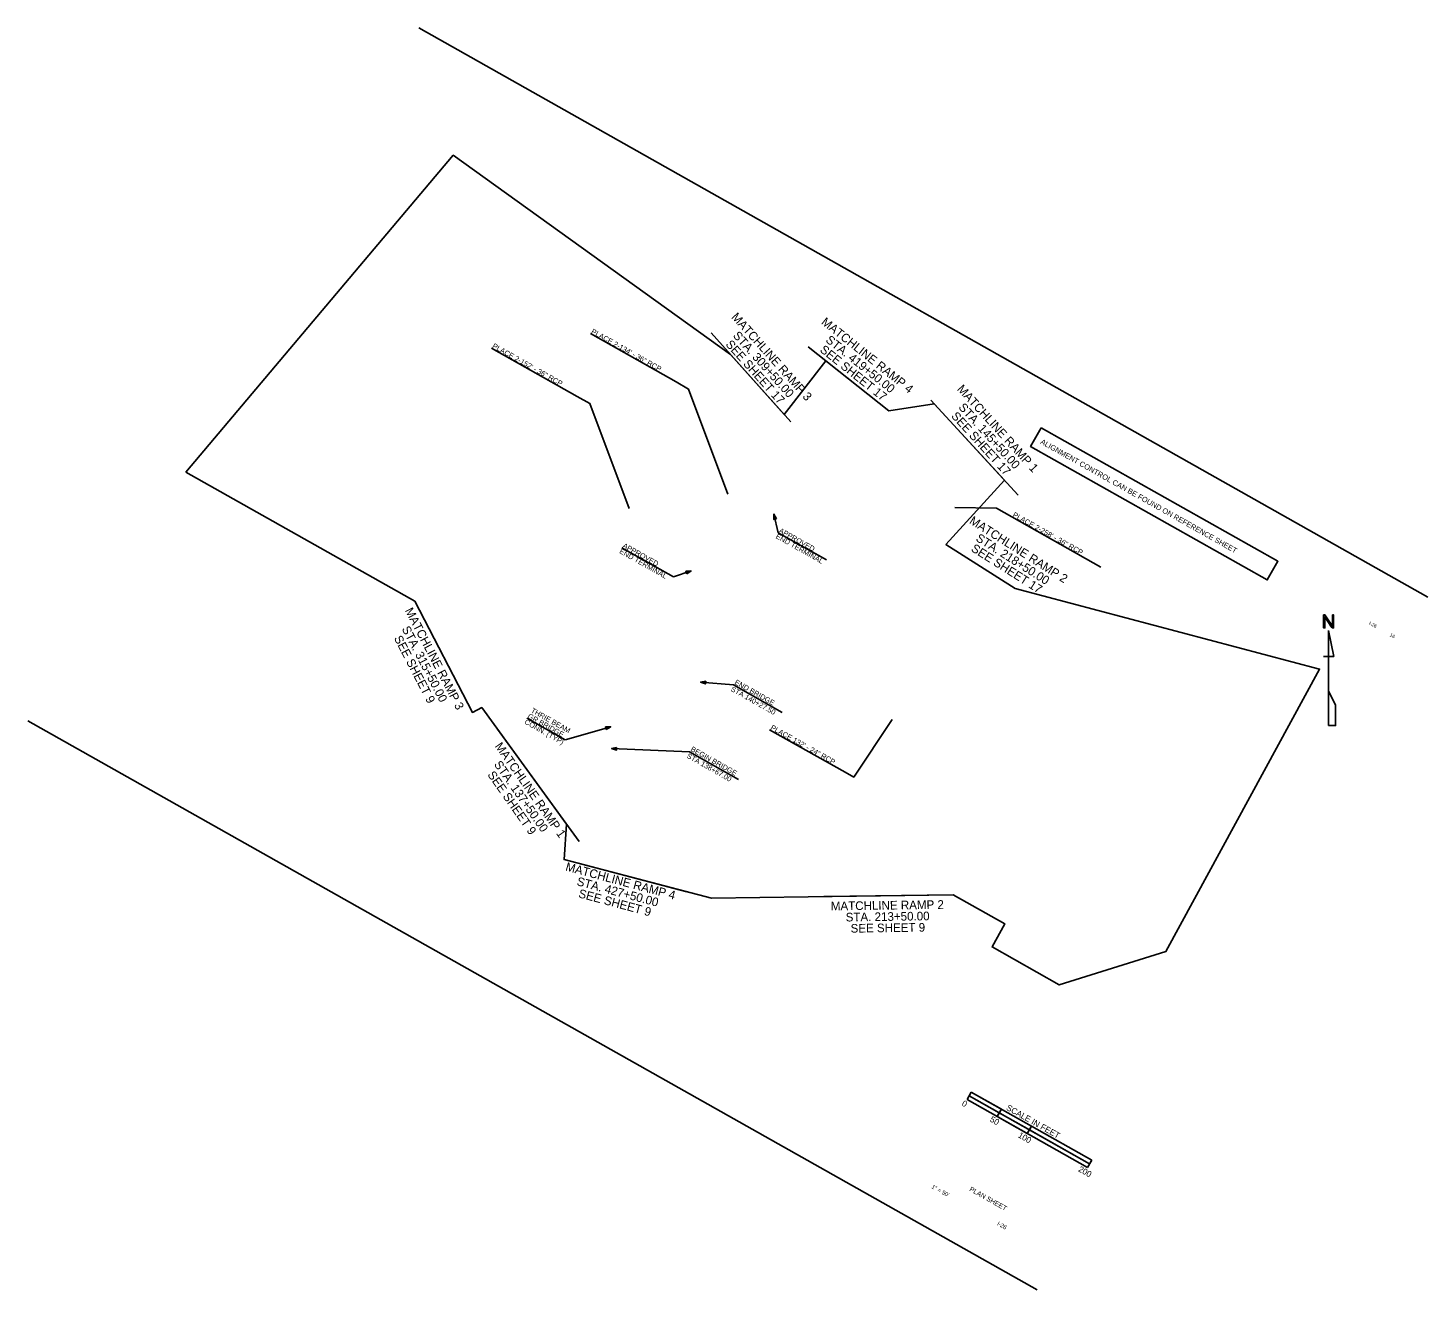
# Model space of a CAD drawing. Extents: x 2220815 to 2222839, y 468833 to 470658.
import ezdxf

# ---------------------------------------------------------------- set-up
doc = ezdxf.new("R2010")
doc.units = 0
for name, color, linetype in [('North Arrow', 7, 'Continuous'), ('RD_HY_Misc', 7, 'Continuous'), ('RD_PD_Final_TX', 7, 'Continuous'), ('RD_SHT_MatchLine', 7, 'Continuous'), ('RD_SHT_ShtClip', 7, 'Continuous'), ('RD_SHT_TX', 7, 'Continuous')]:
    doc.layers.add(name, color=color, linetype=linetype)

msp = doc.modelspace()

# ---------------------------------------------------------------- linework, layer by layer
at = {"layer": 'North Arrow'}
for p, q in [((2222695.4, 469786.6), (2222695.4, 469749.1)), ((2222702.9, 469749.1), (2222695.4, 469786.6)), ((2222695.4, 469749.1), (2222687.9, 469749.1)), ((2222695.4, 469749.1), (2222695.4, 469699.1)), ((2222695.4, 469749.1), (2222702.9, 469749.1)), ((2222695.4, 469699.1), (2222695.4, 469649.1))]:
    msp.add_line(p, q, dxfattribs=at)
for points in [[(2222688.2, 469793), (2222688.2, 469790.3), (2222689.9, 469790.3), (2222689.9, 469793), (2222689.9, 469806.5), (2222691.9, 469806.5), (2222690.1, 469809.1), (2222688.2, 469809.1), (2222688.2, 469806.5)], [(2222698.8, 469793), (2222700.6, 469790.3), (2222702.5, 469790.3), (2222702.5, 469793), (2222700.8, 469793), (2222691.9, 469806.5), (2222689.9, 469806.5)], [(2222700.8, 469809.1), (2222700.8, 469793), (2222702.5, 469793), (2222702.5, 469809.1)]]:
    msp.add_lwpolyline(points, close=True, dxfattribs=at)
msp.add_lwpolyline([(2222695.4, 469649.1), (2222705.4, 469649.1), (2222705.4, 469679.1), (2222695.4, 469699.1)], dxfattribs=at)
at = {"layer": 'RD_HY_Misc'}
for p, q in [((2221752.1, 470145.9), (2221628.1, 470215.9)), ((2221609.1, 470125), (2221485.1, 470194.9)), ((2222365.9, 469878.3), (2222237.3, 469950.9)), ((2221996.6, 469581.6), (2221887.3, 469643.2))]:
    msp.add_line(p, q, dxfattribs=at)
for points in [[(2221752.1, 470145.9), (2221770.2, 470135.7), (2221826.9, 469983.9)], [(2221609.1, 470125), (2221627.2, 470114.8), (2221684, 469962.9)], [(2222237.3, 469950.9), (2222215, 469963.5), (2222155.1, 469964.4)], [(2221996.6, 469581.6), (2222008.8, 469574.7), (2222064.6, 469657.9)]]:
    msp.add_lwpolyline(points, dxfattribs=at)
at = {"layer": 'RD_PD_Final_TX'}
for p, q in [((2221969.3, 469888.6), (2221899.5, 469928)), ((2221748.1, 469864.3), (2221673.5, 469906.3)), ((2221905.5, 469668), (2221834.9, 469707.9)), ((2221591.6, 469628.5), (2221536.2, 469659.7)), ((2221842.3, 469571.2), (2221771.3, 469611.3))]:
    msp.add_line(p, q, dxfattribs=at)
for points in [[(2221897, 469948.1), (2221893.5, 469954.8), (2221893.2, 469947.3)], [(2221767.4, 469868.6), (2221773.7, 469872.7), (2221766.2, 469872.3)], [(2221794.8, 469713.2), (2221787.4, 469711.9), (2221794.4, 469709.3)], [(2221651.1, 469643.5), (2221657.5, 469647.4), (2221650, 469647.3)], [(2221666.1, 469617.5), (2221658.7, 469615.9), (2221665.9, 469613.7)]]:
    msp.add_lwpolyline(points, close=True, dxfattribs=at)
for points in [[(2221899.5, 469928), (2221893.5, 469954.8)], [(2221748.1, 469864.3), (2221773.7, 469872.7)], [(2221834.9, 469707.9), (2221787.4, 469711.9)], [(2221591.6, 469628.5), (2221657.5, 469647.4)], [(2221771.3, 469611.3), (2221658.7, 469615.9)]]:
    msp.add_lwpolyline(points, dxfattribs=at)
at = {"layer": 'RD_SHT_MatchLine'}
for p, q in [((2221802.7, 470216.9), (2221917.8, 470088.2)), ((2221942.9, 470196.7), (2222059.8, 470104.2)), ((2222246.8, 469982.2), (2222120.3, 470119.7)), ((2222242.2, 469847.5), (2222142.2, 469911)), ((2221374.2, 469828.9), (2221457.6, 469668.2)), ((2221611.8, 469481.5), (2221493.8, 469643.8)), ((2221767.5, 469408.8), (2221590, 469455.3)), ((2222152.8, 469404.5), (2221965.7, 469401.8))]:
    msp.add_line(p, q, dxfattribs=at)
at = {"layer": 'RD_SHT_ShtClip'}
msp.add_lwpolyline([(2221043.3, 470015.5), (2221374.2, 469828.9), (2221457.6, 469668.2), (2221471, 469675.1), (2221593.4, 469506.8), (2221590, 469455.3), (2221803.1, 469399.5), (2222152.8, 469404.5), (2222227.5, 469362.4), (2222208.8, 469329.2), (2222306, 469274.3), (2222460.1, 469322.7), (2222682.3, 469730.7), (2222242.2, 469847.5), (2222142.2, 469911), (2222226.7, 470004.1), (2222125.2, 470114.4), (2222059.8, 470104.2), (2221968.4, 470176.5), (2221908.2, 470098.9), (2221830.9, 470185.4), (2221430, 470473.8)], close=True, dxfattribs=at)
at = {"layer": 'RD_SHT_TX'}
for p, q in [((2222839, 469834.7), (2221380.2, 470657.7)), ((2220815.1, 469656.1), (2222274, 468833.1)), ((2222178.8, 469119.3), (2222172.6, 469108.4)), ((2222172.6, 469108.4), (2222346.8, 469010.2)), ((2222178.8, 469119.3), (2222175.7, 469113.9)), ((2222175.7, 469113.9), (2222349.9, 469015.6)), ((2222175.7, 469113.9), (2222219.2, 469089.3)), ((2222178.8, 469119.3), (2222352.9, 469021)), ((2222222.3, 469094.7), (2222178.8, 469119.3)), ((2222222.3, 469094.7), (2222216.2, 469083.9)), ((2222219.2, 469089.3), (2222216.2, 469083.9)), ((2222216.2, 469083.9), (2222259.7, 469059.3)), ((2222219.2, 469089.3), (2222222.3, 469094.7)), ((2222262.8, 469064.7), (2222219.2, 469089.3)), ((2222265.8, 469070.2), (2222259.7, 469059.3)), ((2222259.7, 469059.3), (2222262.8, 469064.7)), ((2222265.8, 469070.2), (2222262.8, 469064.7)), ((2222262.8, 469064.7), (2222349.9, 469015.6)), ((2222352.9, 469021), (2222265.8, 469070.2)), ((2222352.9, 469021), (2222346.8, 469010.2)), ((2222349.9, 469015.6), (2222352.9, 469021))]:
    msp.add_line(p, q, dxfattribs=at)
msp.add_lwpolyline([(2222279.9, 470079.8), (2222622, 469886.8), (2222606.7, 469859.7), (2222264.6, 470052.7)], close=True, dxfattribs=at)

# ---------------------------------------------------------------- texts
at = {"layer": 'RD_HY_Misc'}
for s, p in [('PLACE 2-134\' - 36" RCP', (2221628.5, 470216.8)), ('PLACE 2-152\' - 36" RCP', (2221485.6, 470195.8)), ('PLACE 2-258\' - 36" RCP', (2222237.8, 469951.7)), ('PLACE 132\' - 24" RCP', (2221887.8, 469644.1))]:
    msp.add_text(s, height=7.5, rotation=330.5715, dxfattribs=at).set_placement(p)
at = {"layer": 'RD_PD_Final_TX'}
for s, p in [('APPROVED', (2221899.9, 469928.8)), ('APPROVED', (2221674, 469907.1)), ('END TERMINAL', (2221895.3, 469920.6)), ('END TERMINAL', (2221669.3, 469899)), ('END BRIDGE', (2221835.8, 469709.5)), ('STA 140+27.50', (2221830.3, 469699.7)), ('THRIE BEAM', (2221541.4, 469668.8)), ('CONN. (TYP)', (2221532.1, 469652.3)), ('GR BRIDGE', (2221536.7, 469660.6)), ('STA 138+67.00', (2221766.7, 469603.1)), ('BEGIN BRIDGE', (2221772.3, 469612.9))]:
    msp.add_text(s, height=7.5, rotation=330.5715, dxfattribs=at).set_placement(p)
at = {"layer": 'RD_SHT_MatchLine'}
for s, rotation, p in [('MATCHLINE RAMP 3', 311.8528, (2221831.2, 470239.2)), ('MATCHLINE RAMP 4', 321.3952, (2221960.9, 470230.6)), ('STA. 309+50.00', 311.8528, (2221833.4, 470212.4)), ('SEE SHEET 17', 311.8528, (2221822.8, 470199.8)), ('SEE SHEET 17', 321.3952, (2221958.9, 470190.6)), ('STA. 419+50.00', 321.3952, (2221967.3, 470204.7)), ('MATCHLINE RAMP 1', 312.3322, (2222157.5, 470135)), ('STA. 145+50.00', 312.3322, (2222159.5, 470108.6)), ('SEE SHEET 17', 312.3322, (2222149, 470096)), ('MATCHLINE RAMP 2', 327.5917, (2222175, 469942.2)), ('STA. 218+50.00', 327.5917, (2222184.2, 469917.1)), ('SEE SHEET 17', 327.5917, (2222177.4, 469902.2)), ('MATCHLINE RAMP 3', 297.4295, (2221359.7, 469815.6)), ('STA. 315+50.00', 297.4295, (2221355.1, 469789.1)), ('SEE SHEET 9', 297.4295, (2221343.8, 469775.5)), ('MATCHLINE RAMP 1', 305.0643, (2221489.5, 469619.4)), ('STA. 137+50.00', 305.0643, (2221488.2, 469593)), ('SEE SHEET 9', 305.0643, (2221478.8, 469578)), ('MATCHLINE RAMP 4', 344.9842, (2221591.3, 469439.7)), ('STA. 427+50.00', 344.9842, (2221607.5, 469418.5)), ('SEE SHEET 9', 344.9842, (2221610, 469401)), ('MATCHLINE RAMP 2', 0.8259, (2221975.8, 469381.9)), ('STA. 213+50.00', 0.8259, (2221997.3, 469365.9)), ('SEE SHEET 9', 0.8259, (2222004.4, 469349.7))]:
    msp.add_text(s, height=12.5, rotation=rotation, dxfattribs=at).set_placement(p)
at = {"layer": 'RD_SHT_TX'}
for s, height, p in [('ALIGNMENT CONTROL CAN BE FOUND ON REFERENCE SHEET', 7.656, (2222277.9, 470057.2)), ('I-26', 5, (2222753, 469795.7)), ('16', 5, (2222783, 469778.7)), ('0', 8.75, (2222164.2, 469100.3)), ('50', 8.75, (2222204.8, 469077.3)), ('SCALE IN FEET', 8.75, (2222228.5, 469094.1)), ('100', 8.75, (2222245.5, 469054.4)), ('200', 8.75, (2222332.6, 469005.2)), ('1" = 50\'', 6, (2222120.6, 468980.8)), ('PLAN SHEET', 7, (2222175.4, 468976.8)), ('I-26', 6, (2222215.5, 468927.2))]:
    msp.add_text(s, height=height, rotation=330.5715, dxfattribs=at).set_placement(p)

doc.saveas('drawing.dxf')
